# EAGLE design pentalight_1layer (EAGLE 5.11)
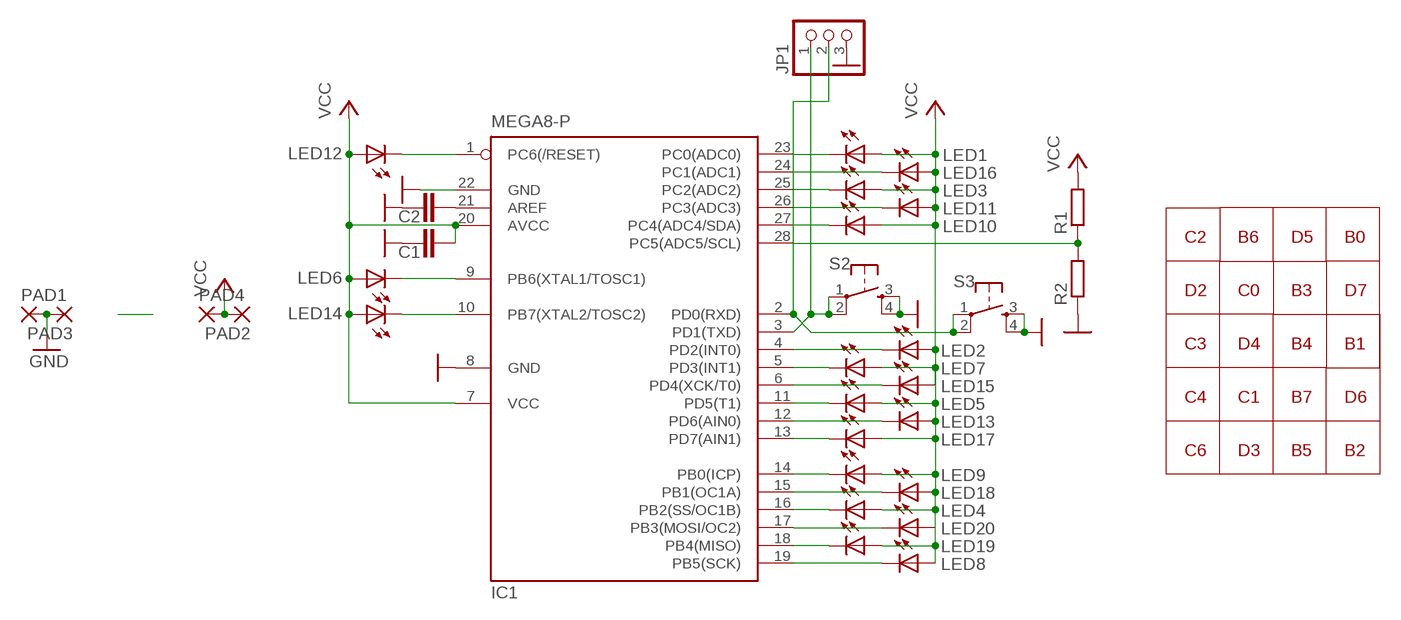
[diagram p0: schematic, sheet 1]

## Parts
C1  C-EU025-024X044  [C025-024X044]
C2  C-EU025-024X044  [C025-024X044]
IC1  MEGA8-P  [DIL28-3]
JP1  PINHD-1X3  [1X03]
LED1  LED5MM  [LED5MM]
LED2  LED5MM  [LED5MM]
LED3  LED5MM  [LED5MM]
LED4  LED5MM  [LED5MM]
LED5  LED5MM  [LED5MM]
LED6  LED5MM  [LED5MM]
LED7  LED5MM  [LED5MM]
LED8  LED5MM  [LED5MM]
LED9  LED5MM  [LED5MM]
LED10  LED5MM  [LED5MM]
LED11  LED5MM  [LED5MM]
LED12  LED5MM  [LED5MM]
LED13  LED5MM  [LED5MM]
LED14  LED5MM  [LED5MM]
LED15  LED5MM  [LED5MM]
LED16  LED5MM  [LED5MM]
LED17  LED5MM  [LED5MM]
LED18  LED5MM  [LED5MM]
LED19  LED5MM  [LED5MM]
LED20  LED5MM  [LED5MM]
PAD1  SMD5  [SMD2,54-5,08]
PAD2  SMD5  [SMD2,54-5,08]
PAD3  2,54/1,0  [2,54/1,0]
PAD4  2,54/1,0  [2,54/1,0]
R1  R-EU_0204/7  [0204/7]
R2  R-EU_0204/7  [0204/7]
S2  TAC_SWITCHPTH  [TACTILE-PTH]
S3  TAC_SWITCHPTH  [TACTILE-PTH]

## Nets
GND: C1.1 C2.1 IC1.8(GND) IC1.22(GND) JP1.3 PAD1.1(P) PAD3.1(P) R2.1 S2.3 S2.4 S3.3 S3.4
N$1: IC1.18(PB4(MISO)) LED19.K(C)
N$2: IC1.17(PB3(MOSI/OC2)) LED20.K(C)
N$3: IC1.23(PC0(ADC0)) LED1.K(C)
N$4: IC1.4(PD2(INT0)) LED2.K(C)
N$5: IC1.25(PC2(ADC2)) LED3.K(C)
N$6: IC1.16(PB2(SS/OC1B)) LED4.K(C)
N$7: IC1.11(PD5(T1)) LED5.K(C)
N$8: IC1.9(PB6(XTAL1/TOSC1)) LED6.K(C)
N$9: IC1.5(PD3(INT1)) LED7.K(C)
N$10: IC1.19(PB5(SCK)) LED8.K(C)
N$11: IC1.14(PB0(ICP)) LED9.K(C)
N$12: IC1.26(PC3(ADC3)) LED11.K(C)
N$13: IC1.27(PC4(ADC4/SDA)) LED10.K(C)
N$14: IC1.1(PC6(/RESET)) LED12.K(C)
N$16: IC1.10(PB7(XTAL2/TOSC2)) LED14.K(C)
N$17: C2.2 IC1.21(AREF)
N$18: IC1.24(PC1(ADC1)) LED16.K(C)
N$19: IC1.13(PD7(AIN1)) LED17.K(C)
N$20: IC1.15(PB1(OC1A)) LED18.K(C)
N$21: IC1.12(PD6(AIN0)) LED13.K(C)
N$22: IC1.6(PD4(XCK/T0)) LED15.K(C)
N$23: IC1.28(PC5(ADC5/SCL)) R1.1 R2.2
N$27: IC1.3(PD1(TXD)) JP1.1 S2.1 S2.2
N$28: IC1.2(PD0(RXD)) JP1.2 S3.1 S3.2
VCC: C1.2 IC1.7(VCC) IC1.20(AVCC) LED1.A LED2.A LED3.A LED4.A LED5.A LED6.A LED7.A LED8.A LED9.A LED10.A LED11.A LED12.A LED13.A LED14.A LED15.A LED16.A LED17.A LED18.A LED19.A LED20.A PAD2.1(P) PAD4.1(P) R1.2

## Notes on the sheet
- C2 | B6 | D5 | B0
- D2 | C0 | B3 | D7
- C3 | D4 | B4 | B1
- C4 | C1 | B7 | D6
- C6 | D3 | B5 | B2

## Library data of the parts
C1 C2 = resistor:C-EU: CAPACITOR, European symbol
IC1 = atmel:MEGA8-P: MICROCONTROLLER 8 Kbytes FLASH, 1 kbytes SRAM, 512 bytes EEPROM, USART, 4-channel 10 bit ADC, 2-channel 8 bit ADC Pin compatible with Atmega48, ATMega88, ATMega168 Source: avr.lbr; OC_FARNELL: unknown; OC_NEWARK: unknown
JP1 = pinhead:PINHD-1X3: PIN HEADER
LED1-LED20 = SparkFun:LED: LEDs
PAD1 PAD2 = wirepad:SMD5: SMD PAD
PAD3 PAD4 = wirepad:2,54/1,0: THROUGH-HOLE PAD
R1 R2 = resistor:R-EU_: RESISTOR, European symbol
S2 S3 = SparkFun:TAC_SWITCH: Momentary Switch Button commonly used for reset or general input. Spark Fun Electronics SKU : COM-00097

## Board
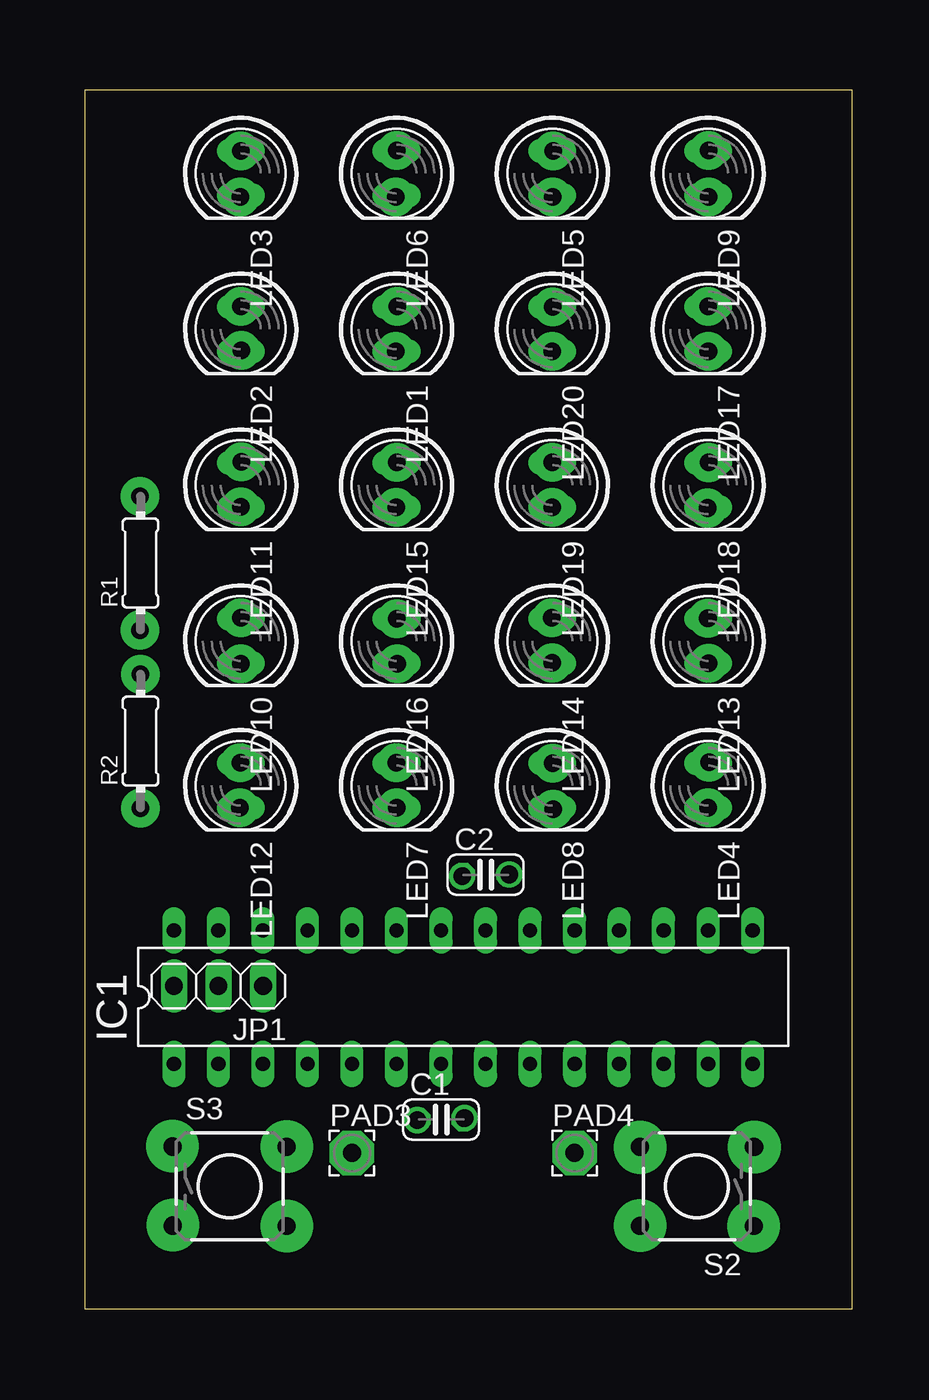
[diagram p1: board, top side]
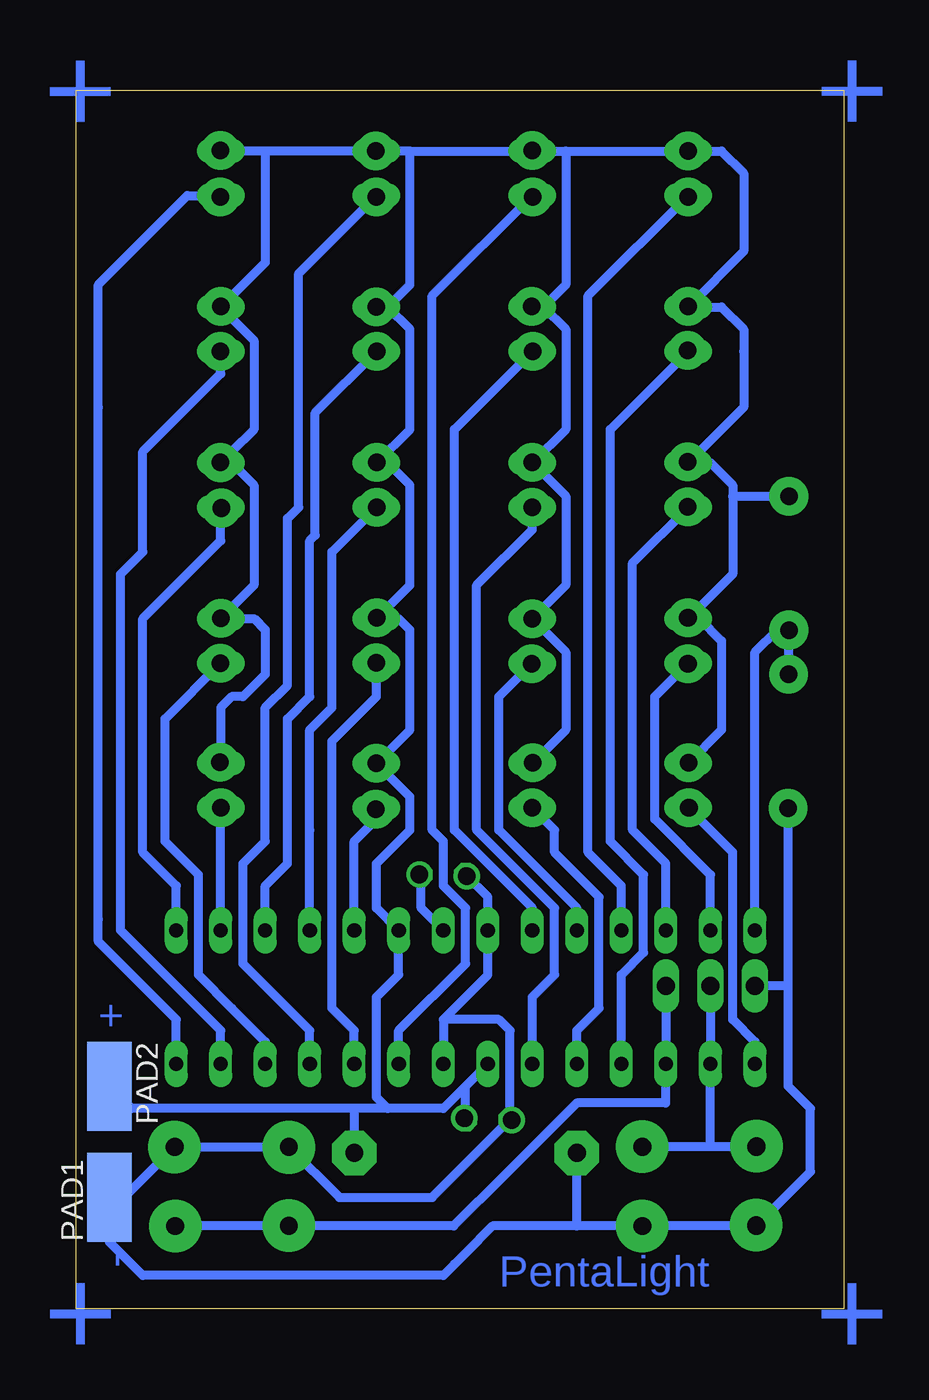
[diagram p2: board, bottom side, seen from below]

Size 43.8 x 69.52 mm. Coordinates in mm from the lower left corner, seen from the top.
Outline: 0,0 43.8,0 43.8,69.52 0,69.52 0,0
Copper layers (1*16): Top 0.035mm / dielectric 1.5mm / Bottom 0.035mm
Design rules "default": minimum track width 10mil, minimum drill 24mil, track to track 8mil, track to pad 8mil, pad to pad 8mil, via to via 8mil, smd to smd 8mil, copper to edge 40mil, drill to drill 8mil, minimum pad ring 10mil, minimum via ring 8mil, stop-mask expansion 4mil, vias tented up to drill 0mil, thermal gap 10mil

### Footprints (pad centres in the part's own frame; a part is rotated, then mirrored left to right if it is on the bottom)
C025-024X044 = drill 0.813 octagon: 1 -1.27,0; 2 1.27,0
DIL28-3 = drill 0.813 long: 1 -16.51,-3.81; 2 -13.97,-3.81; 3 -11.43,-3.81; 4 -8.89,-3.81; 5 -6.35,-3.81; 6 -3.81,-3.81; 7 -1.27,-3.81; 8 1.27,-3.81; 9 3.81,-3.81; 10 6.35,-3.81; 11 8.89,-3.81; 12 11.43,-3.81; 13 13.97,-3.81; 14 16.51,-3.81; 15 16.51,3.81; 16 13.97,3.81; 17 11.43,3.81; 18 8.89,3.81; 19 6.35,3.81; 20 3.81,3.81; 21 1.27,3.81; 22 -1.27,3.81; 23 -3.81,3.81; 24 -6.35,3.81; 25 -8.89,3.81; 26 -11.43,3.81; 27 -13.97,3.81; 28 -16.51,3.81
1X03 = drill 1.016 long: 1 -2.54,0; 2 0,0; 3 2.54,0
LED5MM = drill 0.813 pad 1.372 long: A -1.27,0; K 1.27,0
SMD2,54-5,08 = smd 2.54 x 5.08: 1 0,0
2,54/1,0 = drill 1.016 pad 2.54 octagon: 1 0,0
0204/7 = drill 0.813 octagon: 1 -3.81,0; 2 3.81,0
TACTILE-PTH = drill 1.016 pad 1.88 round: 1 -3.251,2.261; 2 3.251,2.261; 3 -3.251,-2.261; 4 3.251,-2.261

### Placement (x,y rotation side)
C1  20.32,10.79 0 top
C2  22.86,24.77 0 top
IC1  21.59,17.78 0 top
JP1  7.62,18.41 180 top
LED1  17.78,55.88 270 top
LED2  8.89,55.88 270 top
LED3  8.89,64.77 270 top
LED4  35.56,29.84 270 top
LED5  26.67,64.77 270 top
LED6  17.78,64.77 270 top
LED7  17.78,29.84 270 top
LED8  26.67,29.84 270 top
LED9  35.56,64.77 270 top
LED10  8.89,38.1 270 top
LED11  8.89,46.99 270 top
LED12  8.89,29.84 270 top
LED13  35.56,38.1 270 top
LED14  26.67,38.1 270 top
LED15  17.78,46.99 270 top
LED16  17.78,38.1 270 top
LED17  35.56,55.88 270 top
LED18  35.56,46.99 270 top
LED19  26.67,46.99 270 top
LED20  26.67,55.88 270 top
PAD1  41.91,6.35 0 bottom
PAD2  41.91,12.7 180 bottom
PAD3  15.24,8.89 0 top
PAD4  27.94,8.89 0 top
R1  3.17,42.55 90 top
R2  3.17,32.38 90 top
S2  34.92,6.99 180 top
S3  8.25,6.99 0 top

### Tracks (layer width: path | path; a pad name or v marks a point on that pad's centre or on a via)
GND
  Bottom 0.5: 22.86,16.51 IC1.8 | 22.86,16.51 20.32,19.05 IC1.22 20.32,23.5 C2.1 | 22.86,16.51 19.69,16.51 19.05,15.88 C1.1 23.49,6.35 25.4,6.35 28.78,6.35 S2.4 S2.3 41.07,6.35 PAD1.1 | 15.24,4.72 S3.4 S3.3 1.9,7.82 1.9,11.43 3.17,12.7 3.17,18.41 | 15.24,4.72 20.04,4.72 21.59,3.17 22.22,2.54 22.86,1.91 40,1.91 41.91,3.81 PAD1.1 | PAD1.1 41.27,5.71 | 3.17,18.41 R2.1 | 15.24,4.72 PAD3.1 | 3.17,18.41 JP1.3
N$1
  Bottom 0.5: LED19.K 29.21,43.18 29.21,34.29 30.48,33.02 30.48,27.3 IC1.18
N$2
  Bottom 0.5: LED20.K 30.16,51.12 30.16,44.13 30.48,43.81 30.48,34.92 31.75,33.66 31.75,25.4 33.02,24.13 IC1.17
N$3
  Bottom 0.5: LED1.K 22.22,50.16 22.22,27.3 17.78,22.86 IC1.23
N$4
  Bottom 0.5: LED2.K 13.33,50.16 13.33,26.67 11.43,24.77 11.43,20.32 12.7,19.05 IC1.4
N$5
  Bottom 0.5: LED3.K 14.6,57.78 14.6,26.04 12.7,24.13 IC1.25
N$6
  Bottom 0.5: IC1.16 LED4.K
N$7
  Bottom 0.5: LED5.K 31.11,59.05 31.11,45.72 31.75,45.09 31.75,35.56 33.02,34.29 33.02,26.67 34.29,25.4 34.29,19.68 30.48,15.88 IC1.11
N$8
  Bottom 0.5: LED6.K 23.49,57.78 23.49,27.3 22.86,26.67 22.86,24.13 21.59,22.86 21.59,19.68 25.4,15.88 IC1.9
N$9
  Bottom 0.5: LED7.K 16.51,27.3 16.51,26.04 13.97,23.5 13.97,17.14 15.24,15.88 IC1.5
N$10
  Bottom 0.5: LED8.K 26.67,27.94 27.94,26.67 IC1.19
N$11
  Bottom 0.5: IC1.14 38.1,16.51 42.55,20.95 42.55,22.23 42.55,51.44 42.55,58.42 37.47,63.5 LED9.K
N$12
  Bottom 0.5: LED11.K 12.06,42.55 12.06,27.3 10.16,25.4 IC1.26
N$13
  Bottom 0.5: LED10.K 10.8,34.92 10.8,27.94 7.62,24.77 IC1.27
N$14
  Bottom 0.5: LED12.K 6.35,26.04 6.35,16.51 5.08,15.24 IC1.1
N$16
  Bottom 0.5: IC1.10 27.94,15.88 29.21,17.14 29.21,27.3 29.21,32.38 26.67,34.92 LED14.K
N$17
  Bottom 0.5: C2.2 24.13,22.86 IC1.21
N$18
  Bottom 0.5: LED16.K 19.69,34.92 19.69,27.3 15.24,22.86 IC1.24
N$19
  Bottom 0.5: IC1.13 35.56,15.88 41.27,21.59 41.27,41.91 40,43.18 40,48.9 35.56,53.34 LED17.K
N$20
  Bottom 0.5: IC1.15 38.1,24.13 40,26.04 40,39.37 35.56,43.81 LED18.K
N$21
  Bottom 0.5: LED13.K 38.73,33.66 38.73,26.67 36.83,24.77 36.83,19.05 34.92,17.14 33.02,15.24 IC1.12
N$22
  Bottom 0.5: LED15.K 17.78,44.45 20.95,41.27 20.95,27.3 16.51,22.86 16.51,19.05 17.78,17.78 IC1.6
N$23
  Bottom 0.5: IC1.28 5.08,37.47 3.81,38.73 R1.1 R2.2
N$24  (via drill 1 pad 3)
  other vias: 5.01,4.77
N$25  (via drill 1 pad 3)
  other vias: 11.51,4.72
N$26  (via drill 1 pad 3)
  other vias: 4.99,9.28
N$27
  Bottom 0.5: S2.1 S2.2 22.26,4.72 19.37,7.62 16.83,10.16 15.24,11.75 10.16,11.75 IC1.3 JP1.1
N$28
  Bottom 0.5: S3.1 7.62,9.25 | 7.62,9.25 S3.2 | 7.62,9.25 7.62,13.82 7.54,13.89 IC1.2 JP1.2
N$29  (via drill 1 pad 3)
  other vias: 11.51,9.26
N$30  (via drill 1 pad 3)
  other vias: 31.68,4.75
N$31  (via drill 1 pad 3)
  other vias: 38.15,4.73
N$32  (via drill 1 pad 3)
  other vias: 38.2,9.24
N$33  (via drill 1 pad 3)
  other vias: 31.68,9.21
N$34  (via drill 1 pad 2.2)
  other vias: 3.18,28.57
N$35  (via drill 1 pad 2.2)
  other vias: 3.16,36.21
N$36  (via drill 1 pad 2.2)
  other vias: 3.14,38.72
N$37  (via drill 1 pad 2.2)
  other vias: 3.14,46.35
N$38  (via drill 1 pad 2.2)
  other vias: 8.89,66.06
N$39  (via drill 1 pad 2.2)
  other vias: 17.8,66.08
N$40  (via drill 1 pad 2.2)
  other vias: 26.71,66.04
N$41  (via drill 1 pad 2.2)
  other vias: 35.58,66.07
N$42  (via drill 1 pad 2.2)
  other vias: 35.55,57.19
N$43  (via drill 1 pad 2.2)
  other vias: 26.68,57.17
N$44  (via drill 1 pad 2.2)
  other vias: 17.82,57.18
N$45  (via drill 1 pad 2.2)
  other vias: 8.89,57.18
N$46  (via drill 1 pad 2.2)
  other vias: 8.92,48.31
N$47  (via drill 1 pad 2.2)
  other vias: 17.79,48.29
N$48  (via drill 1 pad 2.2)
  other vias: 26.66,48.3
N$49  (via drill 1 pad 2.2)
  other vias: 35.59,48.28
N$50  (via drill 1 pad 2.2)
  other vias: 35.54,39.38
N$51  (via drill 1 pad 2.2)
  other vias: 26.64,39.43
N$52  (via drill 1 pad 2.2)
  other vias: 17.8,39.36
N$53  (via drill 1 pad 2.2)
  other vias: 8.9,39.43
N$54  (via drill 1 pad 2.2)
  other vias: 8.86,31.14
N$55  (via drill 1 pad 2.2)
  other vias: 17.76,31.14
N$56  (via drill 1 pad 2.2)
  other vias: 26.69,31.11
N$57  (via drill 1 pad 2.2)
  other vias: 35.61,31.17
N$58  (via drill 1 pad 2.2)
  other vias: 35.55,28.59
N$59  (via drill 1 pad 2.2)
  other vias: 26.71,28.5
N$60  (via drill 1 pad 2.2)
  other vias: 17.8,28.59
N$61  (via drill 1 pad 2.2)
  other vias: 8.85,28.57
N$62  (via drill 1 pad 2.2)
  other vias: 8.9,36.8
N$63  (via drill 1 pad 2.2)
  other vias: 17.82,36.8
N$64  (via drill 1 pad 2.2)
  other vias: 26.67,36.84
N$65  (via drill 1 pad 2.2)
  other vias: 35.59,36.83
N$66  (via drill 1 pad 2.2)
  other vias: 35.53,45.68
N$67  (via drill 1 pad 2.2)
  other vias: 26.66,45.72
N$68  (via drill 1 pad 2.2)
  other vias: 17.78,45.71
N$69  (via drill 1 pad 2.2)
  other vias: 8.91,45.75
N$70  (via drill 1 pad 2.2)
  other vias: 35.57,54.62
N$71  (via drill 1 pad 2.2)
  other vias: 26.66,54.62
N$72  (via drill 1 pad 2.2)
  other vias: 17.75,54.62
N$73  (via drill 1 pad 2.2)
  other vias: 8.92,54.68
N$74  (via drill 1 pad 2.2)
  other vias: 35.59,63.43
N$75  (via drill 1 pad 2.2)
  other vias: 26.68,63.43
N$76  (via drill 1 pad 2.2)
  other vias: 17.75,63.44
N$77  (via drill 1 pad 2.2)
  other vias: 8.88,63.44
N$78  (via drill 1 pad 1)
  other vias: 24.22,24.78
N$79  (via drill 1 pad 1)
  other vias: 21.52,24.68
N$80  (via drill 1 pad 1)
  other vias: 18.96,10.76
N$81  (via drill 1 pad 1)
  other vias: 21.66,10.88
VCC
  Bottom 0.5: 34.92,48.26 33.66,46.99 33.66,41.27 LED13.A 33.66,39.37 33.02,38.73 33.02,36.2 34.29,34.92 34.92,34.92 35.56,34.29 LED4.A | 34.92,48.26 LED18.A | 34.92,48.26 34.92,48.9 33.66,50.16 33.66,55.24 LED17.A 33.02,59.69 33.02,66.04 | 26.03,57.15 24.77,58.42 24.77,66.04 | 26.03,57.15 24.77,55.88 24.77,50.16 LED19.A 26.03,48.26 24.77,46.99 24.77,41.27 LED14.A 25.4,39.37 24.77,38.73 24.77,33.02 LED8.A 24.77,29.21 24.77,27.3 26.67,25.4 26.67,22.86 IC1.20 25.4,19.05 26.67,17.78 26.67,12.06 26.03,11.43 | 26.03,57.15 LED20.A | 33.02,66.04 LED5.A 24.77,66.04 | 33.02,66.04 LED9.A | 8.25,31.11 LED12.A 6.98,33.02 6.98,38.1 8.25,39.37 LED10.A 6.35,41.91 6.35,46.35 | 24.77,66.04 LED6.A 15.88,66.04 | 17.14,57.15 15.88,58.42 15.88,66.04 | 17.14,57.15 15.88,55.88 15.88,50.16 LED15.A 15.88,46.35 15.88,41.27 LED16.A 15.88,37.47 15.88,33.02 LED7.A | 6.35,46.35 6.35,46.99 7.62,48.26 LED11.A 5.71,51.44 5.71,54.61 5.71,55.88 6.98,57.15 8.25,57.15 LED2.A 5.71,60.33 5.71,64.77 6.98,66.04 LED3.A 15.88,66.04 | 17.14,57.15 LED1.A | 6.35,46.35 R1.2 | 21.59,12.7 IC1.7 | 21.59,12.7 22.86,11.43 26.03,11.43 | C1.2 21.59,12.7 | PAD2.1 40.64,11.43 27.94,11.43 | 26.03,11.43 27.94,11.43 | 27.94,11.43 PAD4.1

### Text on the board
Bottom: + | + | + | - | PentaLight | + | +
